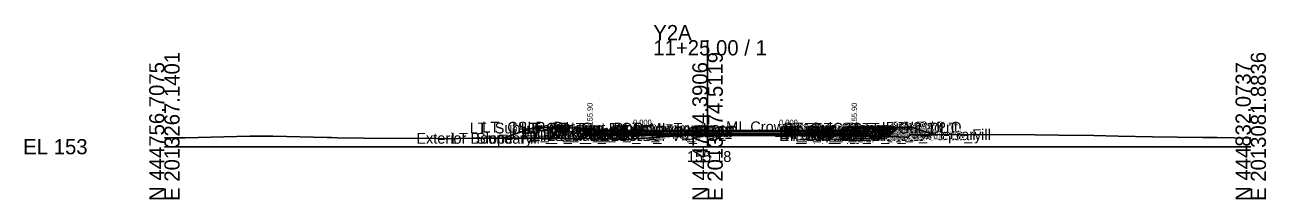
# Model space of a CAD drawing. Extents: x -26 to 203, y -10 to 5517.
# Drawn here: x -25.7 to 202.8, y 2490.3 to 2522.5 of the extents above; entities that cross this region are included whole.
import ezdxf

# ---------------------------------------------------------------- set-up
doc = ezdxf.new("R2010")
doc.units = 0
for name, color, linetype in [('Default', 7, 'Continuous'), ('Exist Cross Section Cell', 7, 'Continuous'), ('Exist XS Center Line Elevation Label', 7, 'Continuous'), ('Exist XS Ground Line', 7, 'Continuous'), ('Prop CMT Conc Surface', 7, 'Continuous'), ('Prop CMT Concrete Structures', 7, 'Continuous'), ('Prop CMT Pvmt Course 1', 7, 'Continuous'), ('Prop CMT Pvmt Course 1 CG', 7, 'Continuous'), ('Prop CMT Pvmt Course 2', 7, 'Continuous'), ('Prop CMT Pvmt Course 3', 7, 'Continuous'), ('Prop CMT Pvmt Surface', 7, 'Continuous'), ('Prop CMT Slope Grass', 7, 'Continuous'), ('Prop CMT Subgrade Earthwork', 7, 'Continuous'), ('Prop XS Earthwork Shape', 7, 'Continuous'), ('Prop XS Hydro Elevations', 7, 'Continuous'), ('Prop XS SE Text', 7, 'Continuous'), ('Prop XS Side Slope Text', 7, 'Continuous'), ('Scratch_Level_0', 7, 'Continuous')]:
    doc.layers.add(name, color=color, linetype=linetype)

msp = doc.modelspace()

# ---------------------------------------------------------------- linework, layer by layer
at = {"layer": 'Exist Cross Section Cell'}
for p, q in [((100, 2500), (100, 2519.65)), ((0, 2500), (100, 2500)), ((100, 2500), (200, 2500))]:
    msp.add_line(p, q, dxfattribs=at)
at = {"layer": 'Exist XS Ground Line'}
msp.add_lwpolyline([(0, 2501.64), (0.88, 2501.64), (3.17, 2501.64), (3.81, 2501.66), (15.73, 2501.92), (19.95, 2501.95), (29.97, 2501.67), (30.75, 2501.67), (31.89, 2501.65), (41.55, 2501.51), (48.17, 2501.56), (52.34, 2501.43), (54.1, 2501.49), (58.43, 2501.56), (63.14, 2501.55), (66.37, 2501.58), (73.94, 2501.56), (84.97, 2501.3), (95.53, 2502.09), (100, 2502.18), (111.62, 2502.4), (112.2, 2502.41), (112.62, 2501.91), (114.2, 2502.01), (115.03, 2502.03), (123.09, 2502.25), (124.27, 2502.29), (127.61, 2502.11), (135.29, 2501.79), (136.31, 2501.73), (136.87, 2501.69), (137.29, 2502.19), (140.53, 2502.19), (142.29, 2502.19), (146.63, 2502.22), (160.32, 2502.19), (164.59, 2502.12), (171.11, 2502.05), (175.59, 2501.95), (181.91, 2501.81), (191.13, 2501.72), (192.71, 2501.7), (193.79, 2501.68), (200, 2501.56)], dxfattribs=at)
at = {"layer": 'Prop CMT Conc Surface'}
for points in [[(78.35, 2502.9), (78.35, 2503.4), (77.85, 2503.4)], [(80.35, 2502.98), (78.35, 2502.9)], [(125.02, 2502.98), (127.02, 2502.9)], [(127.02, 2502.9), (127.03, 2503.4), (127.53, 2503.4)]]:
    msp.add_lwpolyline(points, dxfattribs=at)
at = {"layer": 'Prop CMT Concrete Structures'}
for points in [[(80.35, 2502.98), (78.35, 2502.9), (78.35, 2503.4), (77.85, 2503.4)], [(77.85, 2503.4), (77.85, 2502.39), (80.35, 2502.39)], [(80.35, 2502.39), (80.35, 2502.98)], [(125.02, 2502.98), (127.02, 2502.9), (127.03, 2503.4), (127.53, 2503.4)], [(127.53, 2503.4), (127.52, 2502.39), (125.02, 2502.39)], [(125.02, 2502.39), (125.02, 2502.98)], [(137.06, 2503.6), (131.78, 2503.49)], [(131.78, 2503.49), (131.78, 2503.16)], [(131.78, 2503.16), (137.06, 2503.27)], [(137.06, 2503.27), (137.06, 2503.6)]]:
    msp.add_lwpolyline(points, dxfattribs=at)
at = {"layer": 'Prop CMT Pvmt Course 1'}
for points in [[(100, 2502.98), (80.35, 2502.98)], [(80.35, 2502.98), (80.35, 2502.73)], [(80.35, 2502.73), (100, 2502.73)], [(100, 2502.73), (100, 2502.98)], [(100, 2502.98), (125.02, 2502.98)], [(100, 2502.73), (100, 2502.98)], [(100, 2502.85), (100, 2502.73), (100, 2502.73)], [(125.02, 2502.73), (100, 2502.73)], [(125.02, 2502.98), (125.02, 2502.73)]]:
    msp.add_lwpolyline(points, dxfattribs=at)
at = {"layer": 'Prop CMT Pvmt Course 1 CG'}
for points in [[(80.35, 2502.39), (77.35, 2502.39), (77.02, 2502.06)], [(77.02, 2502.06), (80.35, 2502.06)], [(80.35, 2502.06), (80.35, 2502.39)], [(125.02, 2502.39), (128.02, 2502.39), (128.36, 2502.06)], [(125.02, 2502.06), (125.02, 2502.39)], [(128.36, 2502.06), (125.02, 2502.06)]]:
    msp.add_lwpolyline(points, dxfattribs=at)
at = {"layer": 'Prop CMT Pvmt Course 2'}
for points in [[(100, 2502.73), (80.35, 2502.73)], [(80.35, 2502.73), (80.35, 2502.39)], [(100, 2502.73), (125.02, 2502.73)], [(100, 2502.39), (100, 2502.73)], [(125.02, 2502.73), (125.02, 2502.39)], [(80.35, 2502.39), (100, 2502.39)], [(125.02, 2502.39), (100, 2502.39)]]:
    msp.add_lwpolyline(points, dxfattribs=at)
at = {"layer": 'Prop CMT Pvmt Course 3'}
for points in [[(100, 2502.39), (80.35, 2502.39)], [(80.35, 2502.39), (80.35, 2502.06)], [(80.35, 2502.06), (100, 2502.06)], [(100, 2502.39), (125.02, 2502.39)], [(100, 2502.06), (100, 2502.39)], [(125.02, 2502.06), (100, 2502.06)], [(125.02, 2502.39), (125.02, 2502.06)]]:
    msp.add_lwpolyline(points, dxfattribs=at)
at = {"layer": 'Prop CMT Pvmt Surface'}
for points in [[(100, 2502.98), (80.35, 2502.98)], [(100, 2502.98), (125.02, 2502.98)]]:
    msp.add_lwpolyline(points, dxfattribs=at)
at = {"layer": 'Prop CMT Slope Grass'}
for points in [[(77.85, 2503.4), (68.35, 2503.59), (62.24, 2501.55)], [(127.53, 2503.4), (137.06, 2503.59)], [(137.06, 2503.59), (137.56, 2503.6), (141.79, 2502.19)]]:
    msp.add_lwpolyline(points, dxfattribs=at)
at = {"layer": 'Prop CMT Subgrade Earthwork'}
for points in [[(80.35, 2502.06), (77.02, 2502.06), (75.64, 2503.44)], [(125.02, 2502.06), (128.36, 2502.06), (129.74, 2503.44)], [(100, 2502.06), (80.35, 2502.06)], [(100, 2502.06), (125.02, 2502.06)]]:
    msp.add_lwpolyline(points, dxfattribs=at)
at = {"layer": 'Prop XS Earthwork Shape'}
for points in [[(84.97, 2501.3), (95.1, 2502.06), (80.35, 2502.06), (77.02, 2502.06), (75.64, 2503.44), (68.35, 2503.59), (62.24, 2501.55), (63.14, 2501.55), (66.37, 2501.58), (73.94, 2501.56)], [(137.56, 2503.6), (141.79, 2502.19), (140.53, 2502.19), (137.29, 2502.19), (136.87, 2501.69), (136.31, 2501.73), (135.29, 2501.79), (128.38, 2502.08), (129.74, 2503.44), (131.78, 2503.49), (131.78, 2503.16), (137.06, 2503.27), (137.06, 2503.59)], [(100, 2502.06), (95.1, 2502.06), (95.53, 2502.09), (100, 2502.18), (111.62, 2502.4), (112.2, 2502.41), (112.49, 2502.06)], [(112.49, 2502.06), (116.18, 2502.06), (115.03, 2502.03), (114.2, 2502.01), (112.62, 2501.91)], [(127.61, 2502.11), (128.38, 2502.08), (128.36, 2502.06), (125.02, 2502.06), (116.18, 2502.06), (123.09, 2502.25), (124.27, 2502.29)]]:
    msp.add_lwpolyline(points, close=True, dxfattribs=at)

# ---------------------------------------------------------------- texts
at = {"layer": 'Default'}
msp.add_text('-', height=0.0001, dxfattribs=at).set_placement((0, 2500))
at = {"layer": 'Exist Cross Section Cell'}
for s, p in [('Y2A', (90, 2519.65)), ('11+25.00 / 1', (90, 2516.85)), ('EL 153', (-26, 2498.6))]:
    msp.add_text(s, height=2.8, dxfattribs=at).set_placement(p)
for s, p in [('E 2013267.1401', (2.8, 2490)), ('E 2013174.5119', (102.8, 2490)), ('E 2013081.8836', (202.8, 2490)), ('N 444756.7075', (0, 2490)), ('N 444794.3906', (100, 2490)), ('N 444832.0737', (200, 2490))]:
    msp.add_text(s, height=2.8, rotation=90, dxfattribs=at).set_placement(p)
at = {"layer": 'Exist XS Center Line Elevation Label'}
msp.add_text('155.18', height=2, dxfattribs=at).set_placement((96.2, 2497.18))
at = {"layer": 'Prop XS Hydro Elevations'}
for p in [(78.85, 2503.9), (127.52, 2503.9)]:
    msp.add_text('155.90', height=1, rotation=90, dxfattribs=at).set_placement(p)
at = {"layer": 'Prop XS SE Text'}
msp.add_text('0.000', height=1, dxfattribs=at).set_placement((86.27, 2503.98))
msp.add_text('0.000', height=1, rotation=0, dxfattribs=at).set_placement((113.15, 2503.98))
at = {"layer": 'Prop XS Side Slope Text'}
for rotation, p in [(18.4349, (64.3, 2503.03)), (341.5668, (139.37, 2503.8))]:
    msp.add_text('3:1', height=1, rotation=rotation, dxfattribs=at).set_placement(p)
at = {"layer": 'Scratch_Level_0'}
for s, p in [('Exterior Boundary', (46.38, 2500.55)), ('LT_Slope_Fill', (52.76, 2500.55)), ('LT_Sub_Trench_Out_DLT', (56.2, 2502.44)), ('LT_CSLP_Pnt', (58.52, 2502.59)), ('LT_CG1_Shelf_Out', (63.9, 2501.39)), ('LT_CG_Top_Face', (65.61, 2502.4)), ('LT_CG_Top_BOC', (66.13, 2502.4)), ('LT_CG_Bot_BOC', (66.16, 2501.39)), ('LT_CG_Top_Gut', (66.59, 2501.9)), ('LT_Sub_OEOP', (67.13, 2501.06)), ('LT_Sub_OEOT_CG', (67.72, 2501.06)), ('LT_CG_Bot_IE', (70.26, 2501.39)), ('LT_Sub_OEOT', (70.43, 2501.06)), ('LT_PV2_OEOT', (70.52, 2501.73)), ('LT_PV3_OEOT', (70.52, 2501.39)), ('LT_PV1_OEOT', (71.09, 2501.98)), ('LT_PV2_IEEOP', (85.64, 2501.73)), ('LT_PV1_IEEOP', (86.2, 2501.85)), ('LT_PV2_PGL1', (86.57, 2501.73)), ('LT_PV3_PGL1', (86.57, 2501.39)), ('LT_PV2_PGL', (86.9, 2501.73)), ('LT_PV4_PGL', (86.9, 2501.06)), ('LT_PV1_PGL', (87.46, 2501.98)), ('MI_Face In', (87.58, 2502.14)), ('MI_Top In', (89.29, 2502.39)), ('MI_Crown', (103.41, 2502.67)), ('RT_Sub_OEEOP', (113.16, 2501.06)), ('LT_Sub_OEEOP', (113.2, 2501.06)), ('RT_PV2_OEEOP', (113.25, 2501.73)), ('RT_PV3_OEEOP', (113.25, 2501.39)), ('LT_PV2_OEEOP', (113.3, 2501.73)), ('LT_PV3_OEEOP', (113.3, 2501.39)), ('RT_PV1_OEEOP', (113.82, 2501.85)), ('LT_PV1_OEEOP', (113.87, 2501.85)), ('RT_Sub_Trench_Out_DLT', (113.98, 2502.44)), ('RT_PV2_IEEOP', (114.91, 2501.73)), ('MI_Face Out', (115.26, 2502.14)), ('MI_Top Out', (115.47, 2502.39)), ('RT_PV1_IEEOP', (115.47, 2501.85)), ('RT_PV2_PGL1', (115.83, 2501.73)), ('RT_PV3_PGL1', (115.83, 2501.39)), ('RT_Sub_OEOT_CG', (116.07, 2501.06)), ('RT_PV2_PGL', (116.17, 2501.73)), ('RT_PV4_PGL', (116.17, 2501.06)), ('MI_Bot Out', (116.26, 2501.98)), ('RT_PV1_PGL', (116.73, 2501.98)), ('RT_CG_Top_Face', (117.96, 2502.4)), ('RT_CG1_Shelf_Out', (118.25, 2501.39)), ('RT_CG_Bot_IE', (118.62, 2501.39)), ('RT_Sub_OEOT', (118.78, 2501.06)), ('RT_PV2_OEOT', (118.88, 2501.73)), ('RT_PV3_OEOT', (118.88, 2501.39)), ('RT_CG_Top_Gut', (118.94, 2501.9)), ('RT_PV1_OEOT', (119.44, 2501.98)), ('RT_CG_Top_BOC', (119.49, 2502.4)), ('RT_CG_Bot_BOC', (119.52, 2501.39)), ('RT_Sub_OEOP', (122.15, 2501.06)), ('Exterior Boundary', (129.02, 2501.21)), ('RT_Shld_O', (132.79, 2502.58)), ('CSLP_Pnt', (133.62, 2502.59)), ('RT_Slope_Fill', (135.35, 2501.21))]:
    msp.add_text(s, height=2, dxfattribs=at).set_placement(p)

doc.saveas('drawing.dxf')
